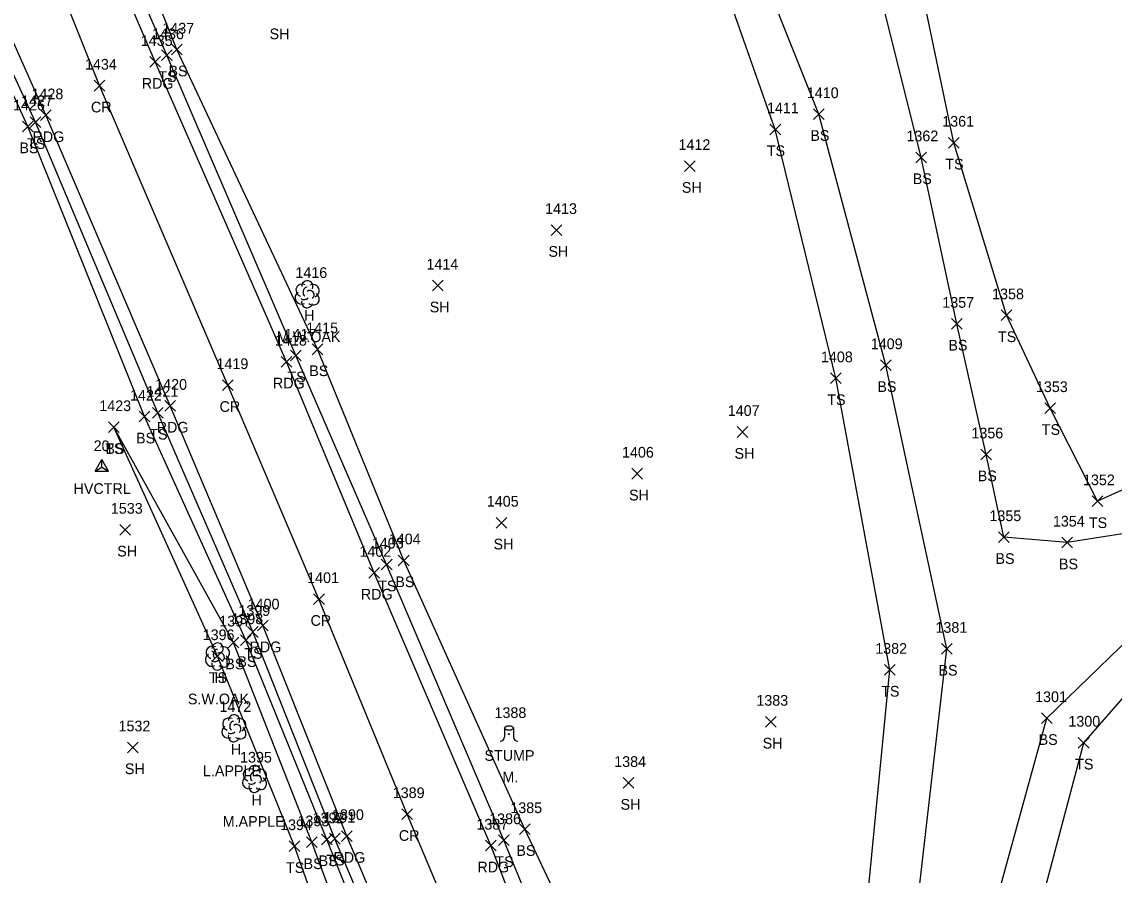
# Model space of a CAD drawing. Extents: x 1472233 to 1475777, y 540726 to 543442.
# Drawn here: x 1475192.5 to 1475396.7, y 542766.7 to 542926.2 of the extents above; entities that cross this region are included whole.
import ezdxf

# ---------------------------------------------------------------- set-up
doc = ezdxf.new("R2010")
doc.units = 0
for name, color, linetype in [('C_A', 7, 'Continuous'), ('C_I', 7, 'Continuous'), ('CPSM', 7, 'Continuous'), ('L_A', 7, 'Continuous'), ('L_C', 7, 'Continuous'), ('L_I', 7, 'Continuous'), ('L_TIC', 7, 'Continuous'), ('LELB', 7, 'Continuous'), ('LTD', 7, 'Continuous'), ('LTS', 7, 'Continuous'), ('P_A', 7, 'Continuous'), ('P_I', 7, 'Continuous'), ('P_TIC', 7, 'Continuous'), ('PEU', 7, 'Continuous'), ('PRC', 7, 'Continuous')]:
    doc.layers.add(name, color=color, linetype=linetype)

msp = doc.modelspace()

# ---------------------------------------------------------------- linework, layer by layer
at = {"layer": 'CPSM'}
for p, q in [((1475206.21, 542842.23), (1475207.46, 542844.39)), ((1475206.21, 542842.23), (1475207.46, 542842.95)), ((1475208.71, 542842.23), (1475207.46, 542844.39)), ((1475207.46, 542842.95), (1475207.46, 542844.39)), ((1475207.46, 542842.95), (1475207.46, 542842.95)), ((1475207.46, 542842.95), (1475208.71, 542842.23)), ((1475206.21, 542842.23), (1475208.71, 542842.23))]:
    msp.add_line(p, q, dxfattribs=at)
at = {"layer": 'L_TIC'}
for points in [[(1475218.58, 542918.95), (1475220.58, 542920.95)], [(1475220.58, 542918.95), (1475218.58, 542920.95)], [(1475220.45, 542920), (1475222.45, 542922)], [(1475222.45, 542920), (1475220.45, 542922)], [(1475340.44, 542907.94), (1475342.44, 542909.94)], [(1475342.44, 542907.94), (1475340.44, 542909.94)], [(1475194.05, 542906.44), (1475196.05, 542908.44)], [(1475196.05, 542906.44), (1475194.05, 542908.44)], [(1475192.59, 542905.64), (1475194.59, 542907.64)], [(1475194.59, 542905.64), (1475192.59, 542907.64)], [(1475332.33, 542905.09), (1475334.33, 542907.09)], [(1475334.33, 542905.09), (1475332.33, 542907.09)], [(1475365.7, 542902.6), (1475367.7, 542904.6)], [(1475367.7, 542902.6), (1475365.7, 542904.6)], [(1475359.58, 542899.86), (1475361.58, 542901.86)], [(1475361.58, 542899.86), (1475359.58, 542901.86)], [(1475316.36, 542898.24), (1475318.36, 542900.24)], [(1475318.36, 542898.24), (1475316.36, 542900.24)], [(1475291.43, 542886.28), (1475293.43, 542888.28)], [(1475293.43, 542886.28), (1475291.43, 542888.28)], [(1475269.24, 542875.89), (1475271.24, 542877.89)], [(1475271.24, 542875.89), (1475269.24, 542877.89)], [(1475375.54, 542870.34), (1475377.54, 542872.34)], [(1475377.54, 542870.34), (1475375.54, 542872.34)], [(1475366.24, 542868.75), (1475368.24, 542870.75)], [(1475368.24, 542868.75), (1475366.24, 542870.75)], [(1475246.78, 542863.98), (1475248.78, 542865.98)], [(1475248.78, 542863.98), (1475246.78, 542865.98)], [(1475242.72, 542862.81), (1475244.72, 542864.81)], [(1475244.72, 542862.81), (1475242.72, 542864.81)], [(1475352.96, 542861.01), (1475354.96, 542863.01)], [(1475354.96, 542861.01), (1475352.96, 542863.01)], [(1475343.63, 542858.57), (1475345.63, 542860.57)], [(1475345.63, 542858.57), (1475343.63, 542860.57)], [(1475383.73, 542852.99), (1475385.73, 542854.99)], [(1475385.73, 542852.99), (1475383.73, 542854.99)], [(1475214.39, 542851.4), (1475216.39, 542853.4)], [(1475216.39, 542851.4), (1475214.39, 542853.4)], [(1475216.9, 542852.12), (1475218.9, 542854.12)], [(1475218.9, 542852.12), (1475216.9, 542854.12)], [(1475208.66, 542849.43), (1475210.66, 542851.43)], [(1475210.66, 542849.43), (1475208.66, 542851.43)], [(1475208.66, 542849.43), (1475210.66, 542851.43)], [(1475210.66, 542849.43), (1475208.66, 542851.43)], [(1475326.21, 542848.53), (1475328.21, 542850.53)], [(1475328.21, 542848.53), (1475326.21, 542850.53)], [(1475371.73, 542844.33), (1475373.73, 542846.33)], [(1475373.73, 542844.33), (1475371.73, 542846.33)], [(1475306.5, 542840.74), (1475308.5, 542842.74)], [(1475308.5, 542840.74), (1475306.5, 542842.74)], [(1475392.53, 542835.58), (1475394.53, 542837.58)], [(1475394.53, 542835.58), (1475392.53, 542837.58)], [(1475281.17, 542831.58), (1475283.17, 542833.58)], [(1475283.17, 542831.58), (1475281.17, 542833.58)], [(1475210.82, 542830.26), (1475212.82, 542832.26)], [(1475212.82, 542830.26), (1475210.82, 542832.26)], [(1475375.04, 542828.87), (1475377.04, 542830.87)], [(1475377.04, 542828.87), (1475375.04, 542830.87)], [(1475386.91, 542827.86), (1475388.91, 542829.86)], [(1475388.91, 542827.86), (1475386.91, 542829.86)], [(1475262.86, 542824.53), (1475264.86, 542826.53)], [(1475264.86, 542824.53), (1475262.86, 542826.53)], [(1475259.68, 542823.75), (1475261.68, 542825.75)], [(1475261.68, 542823.75), (1475259.68, 542825.75)], [(1475234.66, 542811.15), (1475236.66, 542813.15)], [(1475236.66, 542811.15), (1475234.66, 542813.15)], [(1475231.07, 542809.18), (1475233.07, 542811.18)], [(1475233.07, 542809.18), (1475231.07, 542811.18)], [(1475233.34, 542809.62), (1475235.34, 542811.62)], [(1475235.34, 542809.62), (1475233.34, 542811.62)], [(1475364.39, 542808), (1475366.39, 542810)], [(1475366.39, 542808), (1475364.39, 542810)], [(1475228.03, 542806.63), (1475230.03, 542808.63)], [(1475230.03, 542806.63), (1475228.03, 542808.63)], [(1475353.71, 542804.07), (1475355.71, 542806.07)], [(1475355.71, 542804.07), (1475353.71, 542806.07)], [(1475331.47, 542794.37), (1475333.47, 542796.37)], [(1475333.47, 542794.37), (1475331.47, 542796.37)], [(1475383.1, 542795.05), (1475385.1, 542797.05)], [(1475385.1, 542795.05), (1475383.1, 542797.05)], [(1475212.25, 542789.58), (1475214.25, 542791.58)], [(1475214.25, 542789.58), (1475212.25, 542791.58)], [(1475389.97, 542790.46), (1475391.97, 542792.46)], [(1475391.97, 542790.46), (1475389.97, 542792.46)], [(1475304.91, 542782.93), (1475306.91, 542784.93)], [(1475306.91, 542782.93), (1475304.91, 542784.93)], [(1475285.48, 542774.3), (1475287.48, 542776.3)], [(1475287.48, 542774.3), (1475285.48, 542776.3)], [(1475242.45, 542771.12), (1475244.45, 542773.12)], [(1475244.45, 542771.12), (1475242.45, 542773.12)], [(1475245.71, 542771.84), (1475247.71, 542773.84)], [(1475247.71, 542771.84), (1475245.71, 542773.84)], [(1475248.52, 542772.39), (1475250.52, 542774.39)], [(1475250.52, 542772.39), (1475248.52, 542774.39)], [(1475250.01, 542772.52), (1475252.01, 542774.52)], [(1475252.01, 542772.52), (1475250.01, 542774.52)], [(1475281.59, 542772.23), (1475283.59, 542774.23)], [(1475283.59, 542772.23), (1475281.59, 542774.23)]]:
    msp.add_lwpolyline(points, dxfattribs=at)
at = {"layer": 'LELB'}
for points in [[(1475357.79, 542598.07), (1475337.62, 542645.37), (1475320.89, 542687.95), (1475305.38, 542735.27), (1475286.48, 542775.3), (1475263.86, 542825.53), (1475247.78, 542864.98), (1475221.45, 542921), (1475204.55, 542963.46), (1475185.95, 543014.43), (1475167.08, 543062.79), (1475146.02, 543122.64), (1475125.78, 543159.9), (1475115.12, 543181.67), (1475104, 543206.85), (1475117.79, 543217.06), (1475138.26, 543230.93), (1475159.43, 543247.18), (1475205.28, 543252.38), (1475241.74, 543258.24), (1475252.93, 543261.2)], [(1475637.4, 542862.19), (1475558.97, 542854.37), (1475522.58, 542847.01), (1475462.12, 542840.67), (1475427.68, 542835.08), (1475387.91, 542828.86), (1475376.04, 542829.87), (1475372.73, 542845.33), (1475367.24, 542869.75), (1475360.58, 542900.86), (1475350.02, 542943.33), (1475343.16, 542983.21), (1475336.52, 543023.98), (1475293.88, 543048.79), (1475288.8, 543104.08), (1475278.69, 543153.76), (1475270.93, 543215.65), (1475262.61, 543250.76), (1475255.19, 543261.13), (1475252.93, 543261.2), (1475255.17, 543243.69), (1475255.37, 543228.09)], [(1475351.79, 542648.85), (1475354.21, 542700.68), (1475359.1, 542754.23), (1475365.39, 542809), (1475353.96, 542862.01), (1475341.44, 542908.94), (1475326.71, 542945.92), (1475320.21, 542980.33), (1475313.2, 543006.73), (1475301.5, 543020.23), (1475276.06, 543044.38), (1475278.13, 543102.62), (1475267.62, 543150.84), (1475263.86, 543210.05), (1475244.31, 543220.04), (1475212.37, 543223.3), (1475177.58, 543227.73), (1475145.13, 543221.3), (1475130.45, 543212.37)], [(1475634.87, 542874.57), (1475554.98, 542871.91), (1475517.29, 542864.4), (1475459.45, 542859.45), (1475423.85, 542850.23), (1475393.53, 542836.58), (1475384.73, 542853.99), (1475376.54, 542871.34), (1475366.7, 542903.6), (1475357.98, 542945.38), (1475351.35, 542984.74), (1475343.94, 543023.57), (1475303.71, 543049.95), (1475295.55, 543104.95), (1475285.39, 543155.02), (1475274.49, 543216.06)], [(1475324.25, 542586.46), (1475305.93, 542636.69), (1475289.42, 542677.22), (1475270.47, 542721), (1475249.52, 542773.39), (1475234.34, 542810.62), (1475215.39, 542852.4), (1475193.59, 542906.64), (1475186.62, 542921.79), (1475174.11, 542950.33), (1475153.39, 542998.42), (1475132.78, 543047.28), (1475103.54, 543102.91), (1475089.72, 543143.3), (1475075.93, 543173.27), (1475073.78, 543179.43), (1475045.44, 543180.49), (1475026.91, 543174.69), (1475000.68, 543175.19), (1474987.24, 543167.85), (1474972.18, 543161.15)], [(1475351.79, 542648.85), (1475346.73, 542696.7), (1475349.59, 542751.91), (1475354.71, 542805.07), (1475344.63, 542859.57), (1475333.33, 542906.09), (1475320.02, 542943.8), (1475311.36, 542980.78), (1475299.81, 543004.76), (1475278.98, 543018.33)], [(1475354.38, 542596.74), (1475334.54, 542644.47), (1475317.01, 542686.18), (1475299.22, 542732.65), (1475282.59, 542773.23), (1475260.68, 542824.75), (1475243.72, 542863.81), (1475219.58, 542919.95), (1475201.2, 542962.5), (1475181, 543011.96)], [(1475326.62, 542587.53), (1475308.04, 542636.9), (1475291.06, 542677.72), (1475272.88, 542721.7), (1475251.01, 542773.52), (1475235.66, 542812.15), (1475217.9, 542853.12), (1475195.05, 542907.44), (1475188.13, 542922.31)], [(1475364.9, 542633.22), (1475362.27, 542649.42), (1475377.01, 542709.9), (1475373.37, 542757.09), (1475384.1, 542796.05), (1475405.58, 542816.87), (1475452.12, 542824.11), (1475494.38, 542834.77), (1475545.07, 542839.71), (1475588.17, 542847.33), (1475639.9, 542853.98)], [(1475301, 542637.02), (1475281.33, 542675.19), (1475262.73, 542717.77), (1475243.45, 542772.12), (1475229.03, 542807.63), (1475209.66, 542850.43)], [(1475301, 542637.02), (1475285.25, 542675.89), (1475266.59, 542719.21), (1475246.71, 542772.84), (1475232.07, 542810.18), (1475209.66, 542850.43)], [(1475364.9, 542633.22), (1475367.5, 542650.36), (1475387.19, 542714.41), (1475382.09, 542757.87), (1475390.97, 542791.46), (1475406.78, 542809.5), (1475453.92, 542817.47), (1475495.55, 542828.13), (1475546.23, 542831.61), (1475589.95, 542839.98), (1475641.65, 542845.64)]]:
    msp.add_lwpolyline(points, dxfattribs=at)
at = {"layer": 'LTD'}
for p, q in [((1475245.81, 542875.32), (1475245.81, 542875.32)), ((1475245.81, 542875.32), (1475245.81, 542875.32)), ((1475229.03, 542807.63), (1475229.03, 542807.63)), ((1475229.03, 542807.63), (1475229.03, 542807.63)), ((1475232.11, 542794.2), (1475232.11, 542794.2)), ((1475232.11, 542794.2), (1475232.11, 542794.2)), ((1475235.96, 542784.74), (1475235.96, 542784.74)), ((1475235.96, 542784.74), (1475235.96, 542784.74))]:
    msp.add_line(p, q, dxfattribs=at)
for centre in [(1475245.85, 542876.75), (1475229.08, 542809.06), (1475232.15, 542795.63), (1475236.01, 542786.18)]:
    msp.add_arc(centre, 1.05, 335.5272, 180.9563, dxfattribs=at)
for centre, major_axis, ratio, start_param, end_param in [((1475245.01, 542875.98), (1.21, -0.51), 0.895232, 1.570796, 4.712389), ((1475246.85, 542875.9), (-1.14, -0.48), 0.949671, 1.570796, 4.712389), ((1475244.72, 542874.61), (0.58, -1.04), 0.959034, 3.141593, 6.283185), ((1475245.6, 542875.78), (-0.208, -0.792), 0.645439, 3.141593, 6.283185), ((1475246.31, 542875.15), (-0.5, 0.667), 0.989748, 3.141593, 6.283185), ((1475246.81, 542874.48), (-1.09, 0.79), 0.841452, 1.570796, 4.712389), ((1475245.81, 542873.82), (0.26, 1.06), 0.942809, 1.570796, 4.712389), ((1475245.35, 542874.57), (-0.625, -0.083), 0.423636, 0, 3.141593), ((1475227.95, 542806.92), (0.58, -1.04), 0.959034, 3.141593, 6.283185), ((1475228.24, 542808.29), (1.21, -0.51), 0.895232, 1.570796, 4.712389), ((1475228.83, 542808.08), (-0.208, -0.792), 0.645439, 3.141593, 6.283185), ((1475229.53, 542807.46), (-0.5, 0.667), 0.989748, 3.141593, 6.283185), ((1475230.08, 542808.21), (-1.14, -0.48), 0.949671, 1.570796, 4.712389), ((1475229.03, 542806.13), (0.26, 1.06), 0.942809, 1.570796, 4.712389), ((1475228.58, 542806.88), (-0.625, -0.083), 0.423636, 0, 3.141593), ((1475230.03, 542806.79), (-1.09, 0.79), 0.841452, 1.570796, 4.712389), ((1475231.32, 542794.87), (1.21, -0.51), 0.895232, 1.570796, 4.712389), ((1475233.15, 542794.78), (-1.14, -0.48), 0.949671, 1.570796, 4.712389), ((1475231.02, 542793.49), (0.58, -1.04), 0.959034, 3.141593, 6.283185), ((1475231.65, 542793.45), (-0.625, -0.083), 0.423636, 0, 3.141593), ((1475231.9, 542794.66), (-0.208, -0.792), 0.645439, 3.141593, 6.283185), ((1475232.61, 542794.03), (-0.5, 0.667), 0.989748, 3.141593, 6.283185), ((1475233.11, 542793.37), (-1.09, 0.79), 0.841452, 1.570796, 4.712389), ((1475232.11, 542792.7), (0.26, 1.06), 0.942809, 1.570796, 4.712389), ((1475235.17, 542785.41), (1.21, -0.51), 0.895232, 1.570796, 4.712389), ((1475235.76, 542785.2), (-0.208, -0.792), 0.645439, 3.141593, 6.283185), ((1475236.46, 542784.58), (-0.5, 0.667), 0.989748, 3.141593, 6.283185), ((1475237.01, 542785.33), (-1.14, -0.48), 0.949671, 1.570796, 4.712389), ((1475234.88, 542784.03), (0.58, -1.04), 0.959034, 3.141593, 6.283185), ((1475235.97, 542783.24), (0.26, 1.06), 0.942809, 1.570796, 4.712389), ((1475235.51, 542783.99), (-0.625, -0.083), 0.423636, 0, 3.141593), ((1475236.96, 542783.91), (-1.09, 0.79), 0.841452, 1.570796, 4.712389)]:
    msp.add_ellipse(centre, major_axis=major_axis, ratio=ratio, start_param=start_param, end_param=end_param, dxfattribs=at)
at = {"layer": 'LTS'}
for p, q in [((1475282.71, 542794.21), (1475282.71, 542792.55)), ((1475284.38, 542794.05), (1475284.38, 542794.21)), ((1475284.38, 542794.21), (1475284.38, 542792.55)), ((1475283.54, 542793.07), (1475283.54, 542793.07)), ((1475283.54, 542793.07), (1475283.54, 542793.07)), ((1475283.54, 542793.05), (1475283.54, 542793.05))]:
    msp.add_line(p, q, dxfattribs=at)
msp.add_circle((1475283.54, 542793.07), 0.0833, dxfattribs=at)
for centre, start, end in [((1475281.88, 542792.55), 270, 360), ((1475285.21, 542792.55), 180, 270)]:
    msp.add_arc(centre, 0.833, start, end, dxfattribs=at)
msp.add_ellipse((1475283.54, 542794.21), major_axis=(-0.833, 0), ratio=0.5, dxfattribs=at)
at = {"layer": 'P_TIC'}
for points in [[(1475216.41, 542917.69), (1475218.41, 542919.69)], [(1475218.41, 542917.69), (1475216.41, 542919.69)], [(1475205.98, 542913.26), (1475207.98, 542915.26)], [(1475207.98, 542913.26), (1475205.98, 542915.26)], [(1475195.99, 542907.72), (1475197.99, 542909.72)], [(1475197.99, 542907.72), (1475195.99, 542909.72)], [(1475240.93, 542861.67), (1475242.93, 542863.67)], [(1475242.93, 542861.67), (1475240.93, 542863.67)], [(1475230.01, 542857.29), (1475232.01, 542859.29)], [(1475232.01, 542857.29), (1475230.01, 542859.29)], [(1475219.2, 542853.42), (1475221.2, 542855.42)], [(1475221.2, 542853.42), (1475219.2, 542855.42)], [(1475257.36, 542822.21), (1475259.36, 542824.21)], [(1475259.36, 542822.21), (1475257.36, 542824.21)], [(1475247.03, 542817.3), (1475249.03, 542819.3)], [(1475249.03, 542817.3), (1475247.03, 542819.3)], [(1475236.56, 542812.36), (1475238.56, 542814.36)], [(1475238.56, 542812.36), (1475236.56, 542814.36)], [(1475263.52, 542777.11), (1475265.52, 542779.11)], [(1475265.52, 542777.11), (1475263.52, 542779.11)], [(1475252.25, 542773.01), (1475254.25, 542775.01)], [(1475254.25, 542773.01), (1475252.25, 542775.01)], [(1475279.16, 542771.22), (1475281.16, 542773.22)], [(1475281.16, 542771.22), (1475279.16, 542773.22)]]:
    msp.add_lwpolyline(points, dxfattribs=at)
at = {"layer": 'PEU'}
for points in [[(1475500.74, 542247.44), (1475483.72, 542285.1), (1475468.33, 542320.31), (1475452.99, 542356.73), (1475435.12, 542399.51), (1475417.65, 542439.86), (1475393.18, 542498.17), (1475371.46, 542549.57), (1475352.22, 542595.99), (1475331.5, 542643.66), (1475314.88, 542685.29), (1475295.94, 542731.34), (1475280.16, 542772.22), (1475258.36, 542823.21), (1475241.93, 542862.67), (1475217.41, 542918.69), (1475198.88, 542961.72), (1475177.58, 543009.96), (1475156.54, 543059.07), (1475132.79, 543115.63), (1475115.44, 543155.27)], [(1475479.12, 542237.85), (1475461.93, 542278.83), (1475446.81, 542314.13), (1475433.04, 542347.65), (1475413.19, 542392.06), (1475396.09, 542432.46), (1475370.67, 542491.66), (1475350.46, 542540.4), (1475329.23, 542588.78), (1475309.74, 542637.56), (1475293.45, 542677.97), (1475275.03, 542722.66), (1475253.25, 542774.01), (1475237.56, 542813.36), (1475220.2, 542854.42), (1475196.99, 542908.72), (1475177.68, 542952.09), (1475158.12, 543000.84), (1475137.1, 543050.15), (1475113.34, 543107.63), (1475097.32, 543147.51)]]:
    msp.add_lwpolyline(points, dxfattribs=at)
at = {"layer": 'PRC'}
msp.add_lwpolyline([(1475340.99, 542592.55), (1475321.95, 542640.5), (1475304.24, 542682.02), (1475285.94, 542727.1), (1475264.52, 542778.11), (1475248.03, 542818.3), (1475231.01, 542858.29), (1475206.98, 542914.26), (1475189.62, 542957.63), (1475167.76, 543005.52), (1475147.33, 543055.02), (1475123.61, 543111.78), (1475106.14, 543150.71), (1475094.93, 543179.64), (1475085.95, 543198.87), (1475073.06, 543228.65), (1475063.84, 543250.07), (1475052.92, 543275.83), (1475038.81, 543308.89), (1475018.14, 543355.82)], dxfattribs=at)

# ---------------------------------------------------------------- texts
at = {"layer": 'C_A'}
msp.add_text('HVCTRL', height=2, dxfattribs=at).set_placement((1475202.15, 542837.95))
at = {"layer": 'C_I'}
msp.add_text('20', height=2, dxfattribs=at).set_placement((1475205.91, 542845.95))
at = {"layer": 'L_A'}
for s, p in [('SH', (1475238.8, 542922.94)), ('TS', (1475217.99, 542914.95)), ('BS', (1475219.89, 542916)), ('BS', (1475339.88, 542903.94)), ('TS', (1475193.46, 542902.44)), ('BS', (1475192.03, 542901.64)), ('TS', (1475331.74, 542901.09)), ('TS', (1475365.11, 542898.6)), ('BS', (1475359.02, 542895.86)), ('SH', (1475315.85, 542894.24)), ('SH', (1475290.92, 542882.28)), ('SH', (1475268.73, 542871.89)), ('H', (1475245.24, 542870.32)), ('TS', (1475374.95, 542866.34)), ('BS', (1475365.68, 542864.75)), ('BS', (1475246.22, 542859.98)), ('TS', (1475242.13, 542858.81)), ('BS', (1475352.4, 542857.01)), ('TS', (1475343.04, 542854.57)), ('TS', (1475383.14, 542848.99)), ('BS', (1475213.83, 542847.4)), ('TS', (1475216.31, 542848.12)), ('TS', (1475208.07, 542845.43)), ('BS', (1475208.1, 542845.43)), ('SH', (1475325.7, 542844.53)), ('BS', (1475371.17, 542840.33)), ('SH', (1475305.99, 542836.74)), ('TS', (1475391.94, 542831.58)), ('SH', (1475210.31, 542826.26)), ('SH', (1475280.66, 542827.58)), ('BS', (1475374.48, 542824.87)), ('BS', (1475386.35, 542823.86)), ('BS', (1475262.3, 542820.53)), ('TS', (1475259.09, 542819.75)), ('TS', (1475234.07, 542807.15)), ('BS', (1475230.52, 542805.18)), ('BS', (1475232.78, 542805.62)), ('BS', (1475363.83, 542804)), ('TS', (1475227.44, 542802.63)), ('H', (1475228.47, 542802.63)), ('TS', (1475353.12, 542800.07)), ('SH', (1475330.96, 542790.37)), ('BS', (1475382.54, 542791.05)), ('H', (1475231.54, 542789.2)), ('STUMP', (1475278.96, 542788.07)), ('SH', (1475211.74, 542785.58)), ('TS', (1475389.38, 542786.46)), ('H', (1475235.4, 542779.74)), ('SH', (1475304.4, 542778.93)), ('BS', (1475284.92, 542770.3)), ('TS', (1475241.86, 542767.12)), ('BS', (1475245.15, 542767.84)), ('BS', (1475247.96, 542768.39)), ('TS', (1475249.42, 542768.52)), ('TS', (1475281, 542768.23))]:
    msp.add_text(s, height=2, dxfattribs=at).set_placement(p)
at = {"layer": 'L_C'}
for s, p in [('M.W.OAK', (1475240.17, 542866.32)), ('S.W.OAK', (1475223.52, 542798.63)), ('L.APPLE', (1475226.34, 542785.2)), ('M.', (1475282.31, 542784.07)), ('M.APPLE', (1475230.03, 542775.74))]:
    msp.add_text(s, height=2, dxfattribs=at).set_placement(p)
at = {"layer": 'L_I'}
for s, p in [('1436', (1475216.83, 542922.95)), ('1437', (1475218.75, 542924)), ('1410', (1475339.22, 542911.94)), ('1427', (1475192.35, 542910.44)), ('1426', (1475190.84, 542909.64)), ('1411', (1475331.77, 542909.09)), ('1361', (1475364.53, 542906.6)), ('1362', (1475357.84, 542903.86)), ('1412', (1475315.24, 542902.24)), ('1413', (1475290.3, 542890.28)), ('1414', (1475268.12, 542879.89)), ('1416', (1475243.62, 542878.32)), ('1358', (1475373.85, 542874.34)), ('1357', (1475364.54, 542872.75)), ('1415', (1475245.65, 542867.98)), ('1417', (1475241.6, 542866.81)), ('1409', (1475351.18, 542865.01)), ('1408', (1475341.86, 542862.57)), ('1353', (1475382.04, 542856.99)), ('1422', (1475212.7, 542855.4)), ('1421', (1475215.78, 542856.12)), ('1423', (1475206.96, 542853.43)), ('1423', (1475206.96, 542853.43)), ('1407', (1475324.44, 542852.53)), ('1356', (1475369.98, 542848.33)), ('1406', (1475304.67, 542844.74)), ('1352', (1475390.84, 542839.58)), ('1405', (1475279.4, 542835.58)), ('1533', (1475209.13, 542834.26)), ('1355', (1475373.35, 542832.87)), ('1354', (1475385.22, 542831.86)), ('1404', (1475261.08, 542828.53)), ('1403', (1475257.91, 542827.75)), ('1399', (1475232.96, 542815.15)), ('1397', (1475229.38, 542813.18)), ('1398', (1475231.65, 542813.62)), ('1381', (1475363.26, 542812)), ('1396', (1475226.29, 542810.63)), ('1396', (1475226.29, 542810.63)), ('1382', (1475352.01, 542808.07)), ('1383', (1475329.78, 542798.37)), ('1301', (1475381.89, 542799.05)), ('1472', (1475229.42, 542797.2)), ('1388', (1475280.84, 542796.07)), ('1532', (1475210.56, 542793.58)), ('1300', (1475388.11, 542794.46)), ('1395', (1475233.27, 542787.74)), ('1384', (1475303.22, 542786.93)), ('1385', (1475283.79, 542778.3)), ('1393', (1475244.01, 542775.84)), ('1392', (1475246.83, 542776.39)), ('1391', (1475248.88, 542776.52)), ('1386', (1475279.84, 542776.23)), ('1394', (1475240.76, 542775.12))]:
    msp.add_text(s, height=2, dxfattribs=at).set_placement(p)
at = {"layer": 'P_A'}
for s, p in [('RDG', (1475214.9, 542913.69)), ('CR', (1475205.41, 542909.26)), ('RDG', (1475194.48, 542903.72)), ('RDG', (1475239.42, 542857.67)), ('CR', (1475229.45, 542853.29)), ('RDG', (1475217.69, 542849.42)), ('RDG', (1475255.85, 542818.21)), ('CR', (1475246.46, 542813.3)), ('RDG', (1475235.05, 542808.36)), ('CR', (1475262.96, 542773.11)), ('RDG', (1475250.74, 542769.01)), ('RDG', (1475277.64, 542767.22))]:
    msp.add_text(s, height=2, dxfattribs=at).set_placement(p)
at = {"layer": 'P_I'}
for s, p in [('1435', (1475214.72, 542921.69)), ('1434', (1475204.29, 542917.26)), ('1428', (1475194.29, 542911.72)), ('1418', (1475239.81, 542865.67)), ('1419', (1475228.88, 542861.29)), ('1420', (1475217.42, 542857.42)), ('1402', (1475255.59, 542826.21)), ('1401', (1475245.82, 542821.3)), ('1400', (1475234.7, 542816.36)), ('1389', (1475261.82, 542781.11)), ('1390', (1475250.47, 542777.01)), ('1387', (1475277.46, 542775.22))]:
    msp.add_text(s, height=2, dxfattribs=at).set_placement(p)

doc.saveas('drawing.dxf')
